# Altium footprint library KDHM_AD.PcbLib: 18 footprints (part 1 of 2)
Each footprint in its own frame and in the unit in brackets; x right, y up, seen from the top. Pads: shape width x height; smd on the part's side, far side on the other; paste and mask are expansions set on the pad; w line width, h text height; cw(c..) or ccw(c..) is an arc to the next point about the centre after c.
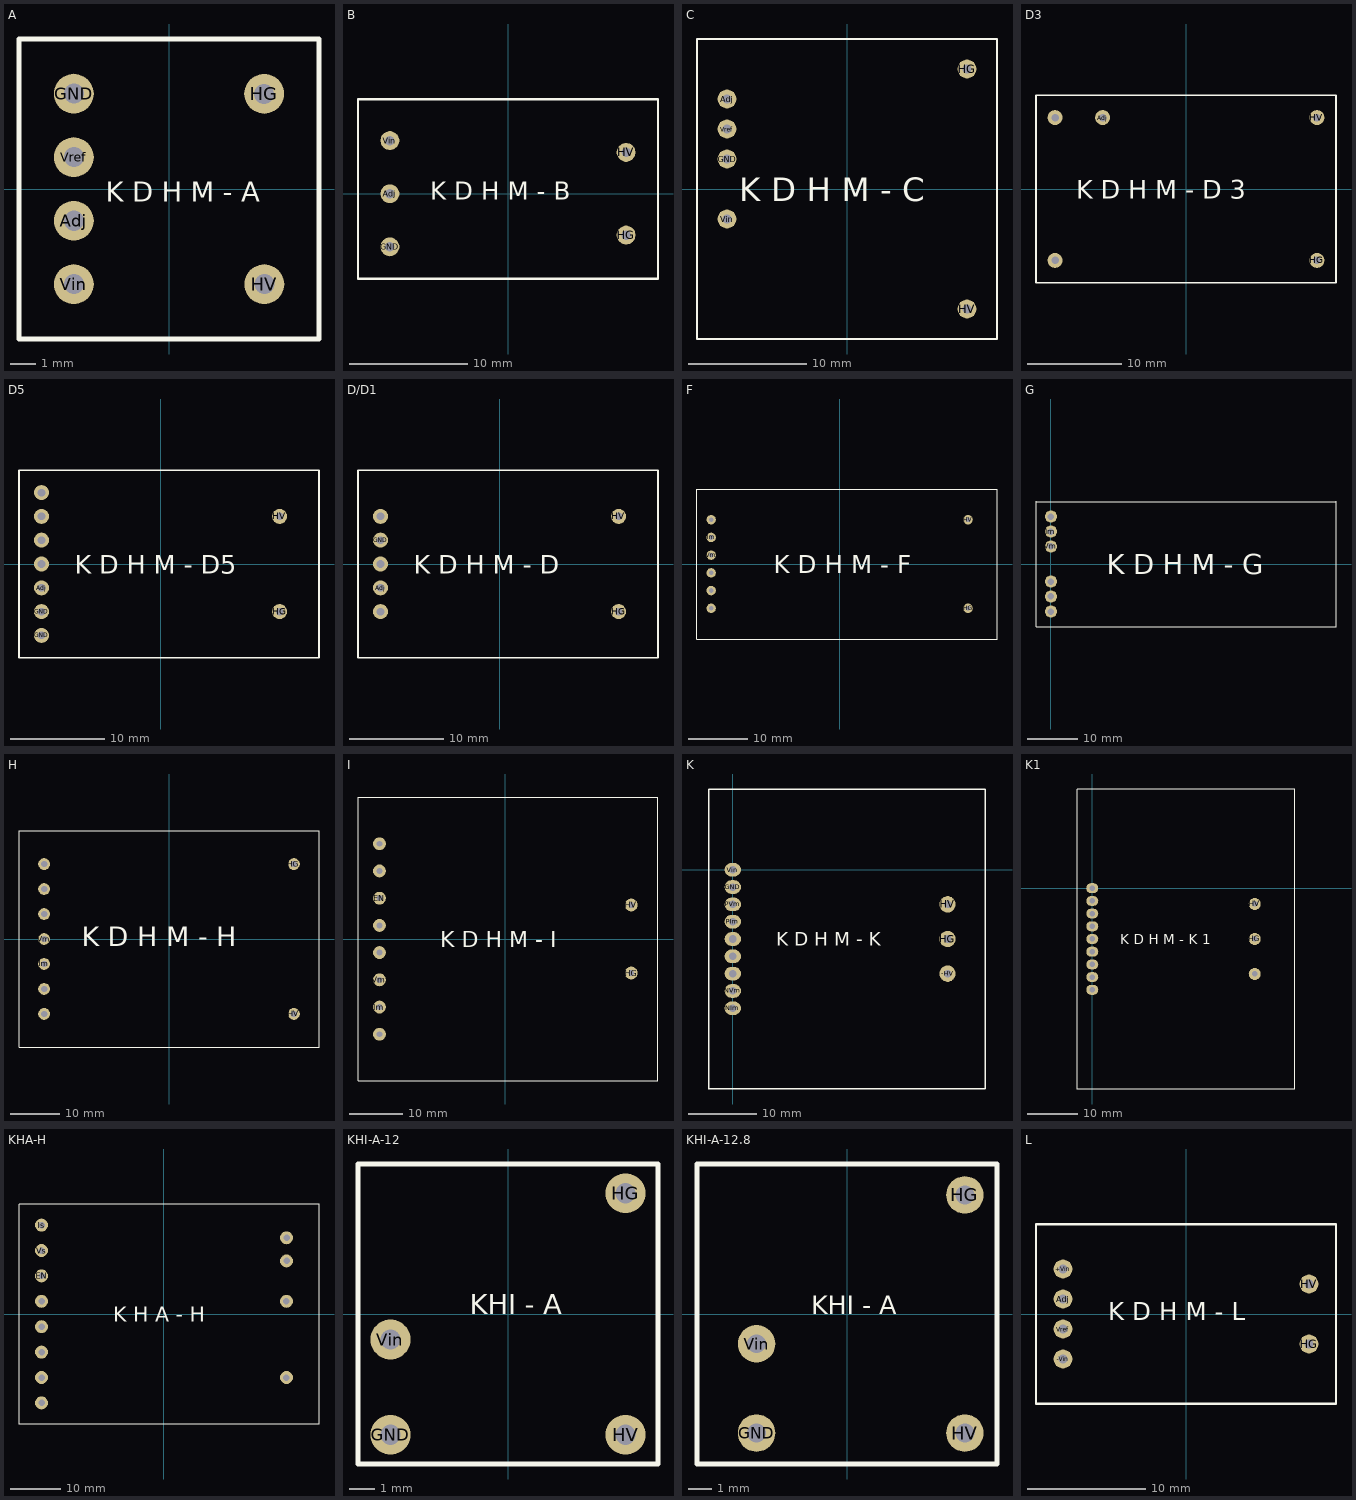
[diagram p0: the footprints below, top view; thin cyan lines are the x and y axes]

## A [mm]
pads (6):
  round 1.6 hole 0.8: Adj(-3.81,-1.27) GND(-3.81,3.81) HG(3.81,3.81) HV(3.81,-3.81) Vin(-3.81,-3.81) Vref(-3.81,1.27)
TopOverlay:
  lines w0.2: -6,-6 -6,6 6,6 6,-6 -6,-6
  text "K D H M - A" at -2.54,-0.508 h0.8

## B [mm]
pads (5):
  round 1.6 hole 0.8: Adj(-10,0) GND(-10,-4.5) HG(10,-3.5) HV(10,3.5) Vin(-10,4.5)
TopOverlay:
  lines w0.2: -12.7,-7.2 12.7,-7.2 12.7,8 -12.7,8 -12.7,-7.2
  text "K D H M - B" at -6.604,-0.508 h1.5

## C [mm]
pads (6):
  round 1.6 hole 0.8: Adj(-10.16,7.62) GND(-10.16,2.54) HG(10.16,10.16) HV(10.16,-10.16) Vin(-10.16,-2.54) Vref(-10.16,5.08)
TopOverlay:
  lines w0.2: -12.7,-12.7 12.7,-12.7 12.7,12.7 -12.7,12.7 -12.7,-12.7
  text "K D H M - C" at -9.144,-1.016 h2

## D3 [mm]
pads (5):
  round 1.6 hole 0.8: +Vin(-13.97,7.62) -Vin(-13.97,-7.62) Adj(-8.89,7.62) HG(13.97,-7.62) HV(13.97,7.62)
TopOverlay:
  lines w0.2: -16,-10 -16,10 16,10 16,-10 -16,-10
  text "K D H M - D 3" at -11.684,-1.016 h2

## D5 [mm]
pads (9):
  round 1.6 hole 0.8: +Vin(-12.7,7.62) Adj(-12.7,-2.54) GND(-12.7,-7.62) GND(-12.7,-5.08) HG(12.7,-5.08) HV(12.7,5.08) Imon(-12.7,2.54) Vmon(-12.7,5.08) Vref(-12.7,0)
TopOverlay:
  lines w0.2: -15.1,-10 16.9,-10 16.9,10 -15.1,10 -15.1,-10
  text "K D H M - D5" at -9.144,-1.016 h2

## D/D1 [mm]
pads (7):
  round 1.6 hole 0.8: +Vin(-12.7,5.08) -Vin(-12.7,-5.08) Adj(-12.7,-2.54) GND(-12.7,2.54) HG(12.7,-5.08) HV(12.7,5.08) Vref(-12.7,0)
TopOverlay:
  lines w0.2: -15.1,-10 16.9,-10 16.9,10 -15.1,10 -15.1,-10
  text "K D H M - D" at -9.144,-1.016 h2

## F [mm]
pads (8):
  round 1.6 hole 0.8: Adj(-21.75,-1.5) GND(-21.75,7.5) HG(21.75,-7.5) HV(21.75,7.5) Im(-21.75,4.5) Vin(-21.75,-7.5) Vm(-21.75,1.5) Vref(-21.75,-4.5)
TopOverlay:
  lines w0.2: -24.15,-12.7 -24.15,12.7 26.65,12.7 26.65,-12.7 -24.15,-12.7
  text "K D H M - F" at -11.176,-1.524 h3

## G [mm]
pads (6):
  round 2.4 hole 1.3: Adj(0,-6.5) GND(0,-9.5) Im(0,6.5) Vin(0,9.5) Vm(0,3.5) Vref(0,-3.5)
TopOverlay:
  lines w0.2: -3,-12.5 57,-12.5 57,12.5 -3,12.5 -3,-12.5
  text "K D H M - G" at 11.176,-2.032 h4

## H [mm]
pads (9):
  round 2.4 hole 1.3: Adj(-25.4,10.16) Com(-25.4,5.08) GND(-25.4,-10.16) HG(25.4,15.24) HV(25.4,-15.24) Im(-25.4,-5.08) Vin(-25.4,-15.24) Vm(-25.4,0) Vref(-25.4,15.24)
TopOverlay:
  lines w0.2: -30.5,-22 30.5,-22 30.5,22 -30.5,22 -30.5,-22
  text "K D H M - H" at -17.78,-1.524 h4

## I [mm]
pads (10):
  round 2.4 hole 1.1: Adj(-23.5,-2.54) EN(-23.5,7.62) GND(-23.5,-17.78) GND(-23.5,12.7) HG(23.5,-6.35) HV(23.5,6.35) Im(-23.5,-12.7) Vin(-23.5,17.78) Vm(-23.5,-7.62) Vref(-23.5,2.54)
TopOverlay:
  lines w0.2: -27.5,-26.5 28.5,-26.5 28.5,26.5 -27.5,26.5 -27.5,-26.5
  text "K D H M - I" at -12.192,-1.524 h3

## K [mm]
pads (12):
  round 2.4 hole 1.1: -HV(31.5,-15.24) HG(31.5,-10.16) HV(31.5,-5.08)
  oval 2.4x2 hole 1.1: GND(0,-2.54) NAdj(0,-15.24) NIm(0,-20.32) NVm(0,-17.78) PAdj(0,-10.16) PIm(0,-7.62) PVm(0,-5.08) Vin(0,0) Vref(0,-12.7)
TopOverlay:
  lines w0.2: -3.5,-32.16 -3.5,11.84 37,11.84 37,-32.16 -3.5,-32.16
  text "K D H M - K" at 6.348,-11.176 h2

## K1 [mm]
pads (12):
  round 2.4 hole 1.1: -HV(32.5,-17.16) HG(32.5,-10.16) HV(32.5,-3.16)
  oval 2.4x2 hole 1.1: GND(0,-2.54) NAdj(0,-15.24) NIm(0,-20.32) NVm(0,-17.78) PAdj(0,-10.16) PIm(0,-7.62) PVm(0,-5.08) Vin(0,0) Vref(0,-12.7)
TopOverlay:
  lines w0.2: -3,-40.16 40.5,-40.16 40.5,19.84 -3,19.84 -3,-40.16
  text "K D H M - K 1" at 5.582,-11.176 h2

## KHA-H [mm]
pads (12):
  round 2.6 hole 1.3: Adj(-24.5,-2.54) Com(24.5,10.61) EN(-24.5,7.62) GND(-24.5,-12.7) GND(-24.5,2.54) GND(24.5,15.24) HVin(24.5,-12.7) HVout(24.5,2.54) Is(-24.5,17.78) Vin(-24.5,-17.78) Vref(-24.5,-7.62) Vs(-24.5,12.7)
TopOverlay:
  lines w0.2: -29,-22 -29,22 31,22 31,-22 -29,-22
  text "K H A - H" at -10.16,-1.524 h3

## KHI-A-12 [mm]
pads (4):
  round 1.6 hole 0.8: GND(-4.7,-4.83) HG(4.7,4.83) HV(4.7,-4.83) Vin(-4.7,-1.02)
TopOverlay:
  lines w0.2: -6,-6 6,-6 6,6 -6,6 -6,-6
  text "KHI - A" at -1.524,0 h0.8

## KHI-A-12.8 [mm]
pads (4):
  round 1.6 hole 0.8: GND(-3.86,-5.08) HG(5.03,5.08) HV(5.03,-5.08) Vin(-3.86,-1.27)
TopOverlay:
  lines w0.2: -6.4,-6.4 6.4,-6.4 6.4,6.4 -6.4,6.4 -6.4,-6.4
  text "KHI - A" at -1.524,0 h0.8

## L [mm]
pads (6):
  round 1.6 hole 0.8: +Vin(-10.414,3.81) -Vin(-10.414,-3.81) Adj(-10.414,1.27) HG(10.414,-2.54) HV(10.414,2.54) Vref(-10.414,-1.27)
TopOverlay:
  lines w0.2: -12.7,-7.6 12.7,-7.6 12.7,7.6 -12.7,7.6 -12.7,-7.6
  text "K D H M - L" at -6.604,-0.508 h1.5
